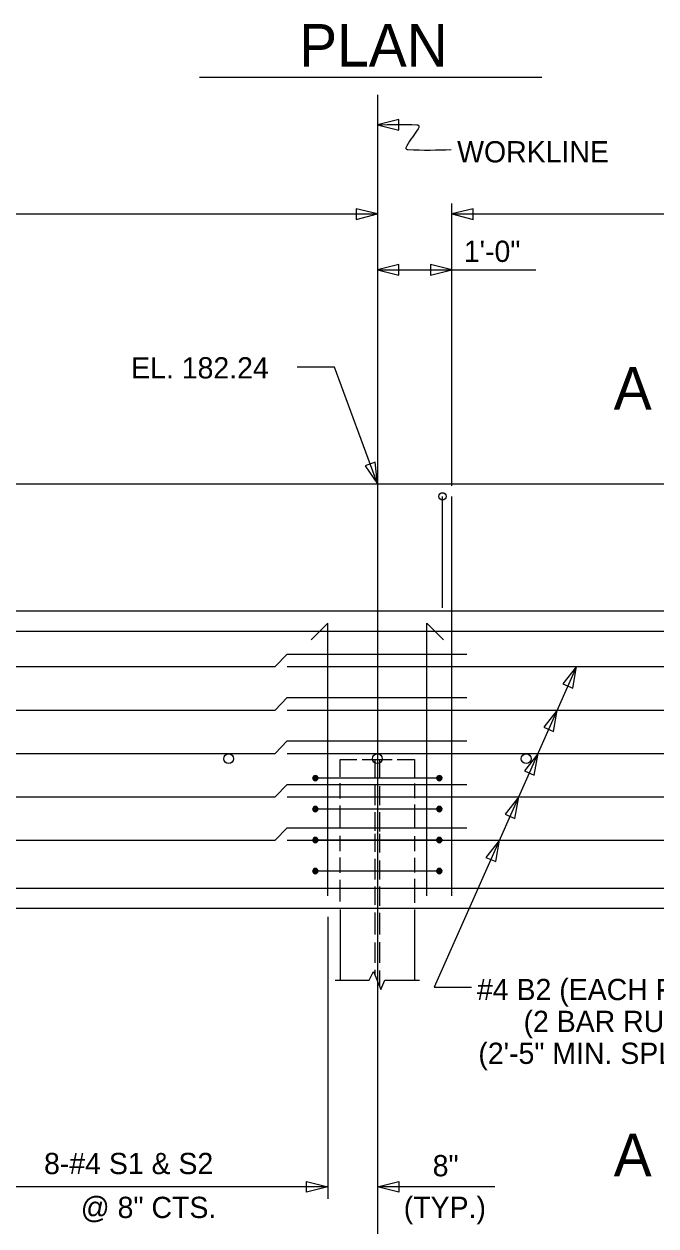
# Model space of a CAD drawing. Extents: x -41 to 251, y -169 to 237.
# Drawn here: x 28.3 to 36.79, y -40.84 to -24.67 of the extents above; entities that cross this region are included whole.
import ezdxf

# ---------------------------------------------------------------- set-up
doc = ezdxf.new("R2010")
doc.units = 0
for name, color, linetype in [('Arrowhead Terminators CELL', 7, 'Continuous'), ('Dimension Lines', 7, 'Continuous'), ('Mis -L- Lines', 7, 'Continuous'), ('Mis Object Lines', 7, 'Continuous'), ('Mis Object Lines Hidden', 7, 'Continuous'), ('Rebar Lines', 7, 'Continuous'), ('Rebar Lines CELL', 7, 'Continuous'), ('Sub End Bent Cap Lines CELL', 7, 'Continuous'), ('Text', 7, 'Continuous'), ('Title Text', 7, 'Continuous')]:
    doc.layers.add(name, color=color, linetype=linetype)

# ---------------------------------------------------------------- blocks, each defined once
blk = doc.blocks.new('AH')
at = {"layer": 'Sub End Bent Cap Lines CELL'}
blk.add_lwpolyline([(0, 0), (-1.25, 0.312), (-1.25, -0.312)], close=True, dxfattribs=at)

msp = doc.modelspace()

# ---------------------------------------------------------------- linework, layer by layer
at = {"layer": 'Arrowhead Terminators CELL'}
for points in [[(33.049, -26.026), (33.335, -26.098), (33.335, -25.955)], [(33.049, -27.225), (32.762, -27.154), (32.762, -27.297)], [(34.049, -27.225), (34.335, -27.297), (34.335, -27.154)], [(33.049, -27.975), (33.335, -28.047), (33.335, -27.904)], [(33.049, -30.857), (33.017, -30.564), (32.883, -30.613)], [(35.726, -33.315), (35.544, -33.548), (35.675, -33.606)], [(35.467, -33.899), (35.285, -34.131), (35.416, -34.189)], [(35.208, -34.482), (35.026, -34.715), (35.157, -34.773)], [(34.949, -35.065), (34.767, -35.298), (34.898, -35.356)], [(34.69, -35.649), (34.508, -35.881), (34.639, -35.939)], [(32.382, -40.315), (32.096, -40.387), (32.096, -40.244)], [(33.049, -40.315), (33.335, -40.244), (33.335, -40.387)]]:
    msp.add_lwpolyline(points, close=True, dxfattribs=at)
at = {"layer": 'Dimension Lines'}
for p, q in [((34.049, -30.881), (34.049, -27.082)), ((17.132, -27.225), (33.049, -27.225)), ((34.049, -27.225), (49.049, -27.225)), ((33.049, -27.975), (35.18, -27.975)), ((35.726, -33.315), (33.812, -37.627)), ((32.382, -36.68), (32.382, -40.475)), ((33.812, -37.627), (34.312, -37.627)), ((32.382, -40.315), (27.715, -40.315)), ((34.627, -40.315), (33.049, -40.315))]:
    msp.add_line(p, q, dxfattribs=at)
msp.add_lwpolyline([(33.049, -30.857), (32.471, -29.286), (31.971, -29.286)], dxfattribs=at)
msp.add_spline([(33.049, -26.026), (33.581, -26.026), (33.598, -26.03), (33.605, -26.04), (33.595, -26.078), (33.519, -26.192), (33.443, -26.306), (33.433, -26.343), (33.44, -26.354), (33.457, -26.358), (34.04, -26.359)], degree=3, dxfattribs=at)
at = {"layer": 'Mis -L- Lines'}
for p, q in [((33.049, -25.623), (33.049, -30.857)), ((33.049, -30.857), (33.049, -42.914))]:
    msp.add_line(p, q, dxfattribs=at)
at = {"layer": 'Mis Object Lines'}
for p, q in [((16.84, -30.857), (39.746, -30.857)), ((17.137, -36.565), (40.197, -36.565))]:
    msp.add_line(p, q, dxfattribs=at)
at = {"layer": 'Mis Object Lines Hidden'}
msp.add_line((13.549, -32.565), (52.549, -32.565), dxfattribs=at)
at = {"layer": 'Rebar Lines'}
for p, q in [((33.924, -32.524), (33.924, -31.024)), ((34.049, -36.399), (34.049, -31.024)), ((32.382, -32.732), (32.158, -32.956)), ((32.382, -36.399), (32.382, -32.732)), ((33.715, -32.732), (33.939, -32.956)), ((33.715, -36.399), (33.715, -32.732)), ((14.256, -32.836), (51.836, -32.836)), ((31.672, -33.315), (31.836, -33.149)), ((31.836, -33.149), (34.253, -33.149)), ((13.797, -33.315), (31.672, -33.315)), ((31.836, -33.315), (52.294, -33.315)), ((31.672, -33.899), (31.836, -33.732)), ((31.836, -33.732), (34.253, -33.732)), ((13.797, -33.899), (31.672, -33.899)), ((31.836, -33.899), (52.294, -33.899)), ((31.672, -34.482), (31.836, -34.315)), ((31.836, -34.315), (34.253, -34.315)), ((33.049, -34.414), (33.049, -36.17)), ((13.797, -34.482), (31.672, -34.482)), ((31.836, -34.482), (52.294, -34.482)), ((33.017, -34.808), (33.017, -34.565)), ((33.08, -34.814), (33.08, -34.565)), ((31.672, -35.065), (31.836, -34.899)), ((31.836, -34.899), (34.253, -34.899)), ((33.017, -35.18), (33.017, -34.901)), ((33.08, -35.18), (33.08, -34.924)), ((13.797, -35.065), (31.672, -35.065)), ((31.836, -35.065), (52.294, -35.065)), ((33.017, -35.522), (33.017, -35.273)), ((33.08, -35.534), (33.08, -35.273)), ((31.672, -35.649), (31.836, -35.482)), ((31.836, -35.482), (34.253, -35.482)), ((33.017, -35.808), (33.017, -35.565)), ((33.08, -35.814), (33.08, -35.565)), ((13.797, -35.649), (31.672, -35.649)), ((31.836, -35.649), (52.294, -35.649)), ((33.017, -36.18), (33.017, -35.901)), ((33.08, -36.18), (33.08, -35.924)), ((14.256, -36.294), (51.836, -36.294)), ((33.017, -36.522), (33.017, -36.273)), ((33.049, -36.275), (33.049, -36.565)), ((33.08, -36.534), (33.08, -36.273)), ((32.548, -36.582), (32.548, -37.534)), ((33.017, -36.917), (33.017, -36.621)), ((33.049, -36.635), (33.049, -37.841)), ((33.08, -36.917), (33.08, -36.627)), ((33.549, -36.582), (33.549, -37.534)), ((33.017, -37.301), (33.017, -37.028)), ((33.08, -37.301), (33.08, -37.022)), ((33.017, -37.469), (33.017, -37.394)), ((33.08, -37.618), (33.08, -37.405))]:
    msp.add_line(p, q, dxfattribs=at)
for points in [[(32.548, -34.799), (32.548, -34.565), (32.771, -34.565)], [(32.846, -34.565), (33.246, -34.565)], [(33.315, -34.565), (33.548, -34.565), (33.548, -34.812)], [(32.548, -35.089), (32.548, -34.882)], [(33.548, -34.888), (33.548, -35.086)], [(32.548, -35.477), (32.548, -35.185)], [(33.548, -35.172), (33.548, -35.493)], [(32.548, -35.799), (32.548, -35.591)], [(33.548, -35.597), (33.548, -35.796)], [(32.548, -36.089), (32.548, -35.882)], [(33.548, -35.888), (33.548, -36.086)], [(32.548, -36.477), (32.548, -36.185)], [(33.548, -36.172), (33.548, -36.493)], [(32.479, -37.535), (32.94, -37.535), (32.995, -37.415), (33.097, -37.66), (33.149, -37.535), (33.615, -37.535)]]:
    msp.add_lwpolyline(points, dxfattribs=at)
for centre, radius in [((33.924, -31.024), 0.0495), ((31.049, -34.554), 0.066), ((33.049, -34.554), 0.066), ((35.049, -34.554), 0.066)]:
    msp.add_circle(centre, radius, dxfattribs=at)
at = {"layer": 'Rebar Lines CELL'}
for p, q in [((33.882, -34.815), (32.215, -34.815)), ((33.882, -35.232), (32.215, -35.232)), ((33.882, -35.649), (32.215, -35.649)), ((33.882, -36.065), (32.215, -36.065))]:
    msp.add_line(p, q, dxfattribs=at)
for points in [[(32.215, -34.78), (32.202, -34.783), (32.19, -34.79), (32.183, -34.802), (32.18, -34.815), (32.183, -34.829), (32.19, -34.84), (32.202, -34.848), (32.215, -34.851), (32.229, -34.848), (32.24, -34.84), (32.248, -34.829), (32.25, -34.815), (32.248, -34.802), (32.24, -34.79), (32.229, -34.783), (32.215, -34.78), (32.215, -34.815), (32.215, -34.851), (32.202, -34.848), (32.215, -34.815), (32.19, -34.84), (32.183, -34.829), (32.215, -34.815), (32.18, -34.815), (32.183, -34.802), (32.215, -34.815), (32.19, -34.79), (32.202, -34.783), (32.215, -34.815), (32.229, -34.783), (32.24, -34.79), (32.215, -34.815), (32.248, -34.802), (32.25, -34.815), (32.215, -34.815), (32.248, -34.829), (32.24, -34.84), (32.215, -34.815), (32.229, -34.848)], [(33.882, -34.78), (33.868, -34.783), (33.857, -34.79), (33.849, -34.802), (33.847, -34.815), (33.849, -34.829), (33.857, -34.84), (33.868, -34.848), (33.882, -34.851), (33.895, -34.848), (33.907, -34.84), (33.914, -34.829), (33.917, -34.815), (33.914, -34.802), (33.907, -34.79), (33.895, -34.783), (33.882, -34.78), (33.882, -34.815), (33.882, -34.851), (33.868, -34.848), (33.882, -34.815), (33.857, -34.84), (33.849, -34.829), (33.882, -34.815), (33.847, -34.815), (33.849, -34.802), (33.882, -34.815), (33.857, -34.79), (33.868, -34.783), (33.882, -34.815), (33.895, -34.783), (33.907, -34.79), (33.882, -34.815), (33.914, -34.802), (33.917, -34.815), (33.882, -34.815), (33.914, -34.829), (33.907, -34.84), (33.882, -34.815), (33.895, -34.848)], [(32.215, -35.197), (32.202, -35.199), (32.19, -35.207), (32.183, -35.218), (32.18, -35.232), (32.183, -35.245), (32.19, -35.257), (32.202, -35.264), (32.215, -35.267), (32.229, -35.264), (32.24, -35.257), (32.248, -35.245), (32.25, -35.232), (32.248, -35.218), (32.24, -35.207), (32.229, -35.199), (32.215, -35.197), (32.215, -35.232), (32.215, -35.267), (32.202, -35.264), (32.215, -35.232), (32.19, -35.257), (32.183, -35.245), (32.215, -35.232), (32.18, -35.232), (32.183, -35.218), (32.215, -35.232), (32.19, -35.207), (32.202, -35.199), (32.215, -35.232), (32.229, -35.199), (32.24, -35.207), (32.215, -35.232), (32.248, -35.218), (32.25, -35.232), (32.215, -35.232), (32.248, -35.245), (32.24, -35.257), (32.215, -35.232), (32.229, -35.264)], [(33.882, -35.197), (33.868, -35.199), (33.857, -35.207), (33.849, -35.218), (33.847, -35.232), (33.849, -35.245), (33.857, -35.257), (33.868, -35.264), (33.882, -35.267), (33.895, -35.264), (33.907, -35.257), (33.914, -35.245), (33.917, -35.232), (33.914, -35.218), (33.907, -35.207), (33.895, -35.199), (33.882, -35.197), (33.882, -35.232), (33.882, -35.267), (33.868, -35.264), (33.882, -35.232), (33.857, -35.257), (33.849, -35.245), (33.882, -35.232), (33.847, -35.232), (33.849, -35.218), (33.882, -35.232), (33.857, -35.207), (33.868, -35.199), (33.882, -35.232), (33.895, -35.199), (33.907, -35.207), (33.882, -35.232), (33.914, -35.218), (33.917, -35.232), (33.882, -35.232), (33.914, -35.245), (33.907, -35.257), (33.882, -35.232), (33.895, -35.264)], [(32.215, -35.613), (32.202, -35.616), (32.19, -35.624), (32.183, -35.635), (32.18, -35.649), (32.183, -35.662), (32.19, -35.674), (32.202, -35.681), (32.215, -35.684), (32.229, -35.681), (32.24, -35.674), (32.248, -35.662), (32.25, -35.649), (32.248, -35.635), (32.24, -35.624), (32.229, -35.616), (32.215, -35.613), (32.215, -35.649), (32.215, -35.684), (32.202, -35.681), (32.215, -35.649), (32.19, -35.674), (32.183, -35.662), (32.215, -35.649), (32.18, -35.649), (32.183, -35.635), (32.215, -35.649), (32.19, -35.624), (32.202, -35.616), (32.215, -35.649), (32.229, -35.616), (32.24, -35.624), (32.215, -35.649), (32.248, -35.635), (32.25, -35.649), (32.215, -35.649), (32.248, -35.662), (32.24, -35.674), (32.215, -35.649), (32.229, -35.681)], [(33.882, -35.613), (33.868, -35.616), (33.857, -35.624), (33.849, -35.635), (33.847, -35.649), (33.849, -35.662), (33.857, -35.674), (33.868, -35.681), (33.882, -35.684), (33.895, -35.681), (33.907, -35.674), (33.914, -35.662), (33.917, -35.649), (33.914, -35.635), (33.907, -35.624), (33.895, -35.616), (33.882, -35.613), (33.882, -35.649), (33.882, -35.684), (33.868, -35.681), (33.882, -35.649), (33.857, -35.674), (33.849, -35.662), (33.882, -35.649), (33.847, -35.649), (33.849, -35.635), (33.882, -35.649), (33.857, -35.624), (33.868, -35.616), (33.882, -35.649), (33.895, -35.616), (33.907, -35.624), (33.882, -35.649), (33.914, -35.635), (33.917, -35.649), (33.882, -35.649), (33.914, -35.662), (33.907, -35.674), (33.882, -35.649), (33.895, -35.681)], [(32.215, -36.03), (32.202, -36.033), (32.19, -36.04), (32.183, -36.052), (32.18, -36.065), (32.183, -36.079), (32.19, -36.09), (32.202, -36.098), (32.215, -36.101), (32.229, -36.098), (32.24, -36.09), (32.248, -36.079), (32.25, -36.065), (32.248, -36.052), (32.24, -36.04), (32.229, -36.033), (32.215, -36.03), (32.215, -36.065), (32.215, -36.101), (32.202, -36.098), (32.215, -36.065), (32.19, -36.09), (32.183, -36.079), (32.215, -36.065), (32.18, -36.065), (32.183, -36.052), (32.215, -36.065), (32.19, -36.04), (32.202, -36.033), (32.215, -36.065), (32.229, -36.033), (32.24, -36.04), (32.215, -36.065), (32.248, -36.052), (32.25, -36.065), (32.215, -36.065), (32.248, -36.079), (32.24, -36.09), (32.215, -36.065), (32.229, -36.098)], [(33.882, -36.03), (33.868, -36.033), (33.857, -36.04), (33.849, -36.052), (33.847, -36.065), (33.849, -36.079), (33.857, -36.09), (33.868, -36.098), (33.882, -36.101), (33.895, -36.098), (33.907, -36.09), (33.914, -36.079), (33.917, -36.065), (33.914, -36.052), (33.907, -36.04), (33.895, -36.033), (33.882, -36.03), (33.882, -36.065), (33.882, -36.101), (33.868, -36.098), (33.882, -36.065), (33.857, -36.09), (33.849, -36.079), (33.882, -36.065), (33.847, -36.065), (33.849, -36.052), (33.882, -36.065), (33.857, -36.04), (33.868, -36.033), (33.882, -36.065), (33.895, -36.033), (33.907, -36.04), (33.882, -36.065), (33.914, -36.052), (33.917, -36.065), (33.882, -36.065), (33.914, -36.079), (33.907, -36.09), (33.882, -36.065), (33.895, -36.098)]]:
    msp.add_lwpolyline(points, dxfattribs=at)
at = {"layer": 'Title Text'}
msp.add_line((30.658, -25.384), (35.26, -25.384), dxfattribs=at)

# ---------------------------------------------------------------- block references
at = {"layer": 'Arrowhead Terminators CELL', "xscale": 0.2288, "yscale": 0.2288}
msp.add_blockref('AH', (34.049, -27.975), dxfattribs=at)

# ---------------------------------------------------------------- texts
at = {"layer": 'Text'}
for s, height, p in [('WORKLINE', 0.286, (34.121, -26.531)), ('1\'-0"', 0.286, (34.21, -27.87)), ('EL. 182.24', 0.286, (29.738, -29.438)), ('#4 B2 (EACH FACE)', 0.286, (34.388, -37.802)), ('(2 BAR RUNS)', 0.286, (35.014, -38.231)), ('(2\'-5" MIN. SPLICE)', 0.286, (34.406, -38.66)), ('8-#4 S1 & S2', 0.286, (28.567, -40.143)), ('8"', 0.286, (33.792, -40.172)), ('@ 8" CTS.', 0.2865, (29.06, -40.734)), ('(TYP.)', 0.286, (33.403, -40.733))]:
    msp.add_text(s, height=height, dxfattribs=at).set_placement(p)
at = {"layer": 'Title Text'}
for s, p in [('PLAN', (31.997, -25.241)), ('A', (36.226, -29.856)), ('A', (36.226, -40.172))]:
    msp.add_text(s, height=0.572, rotation=0, dxfattribs=at).set_placement(p)

doc.saveas('drawing.dxf')
